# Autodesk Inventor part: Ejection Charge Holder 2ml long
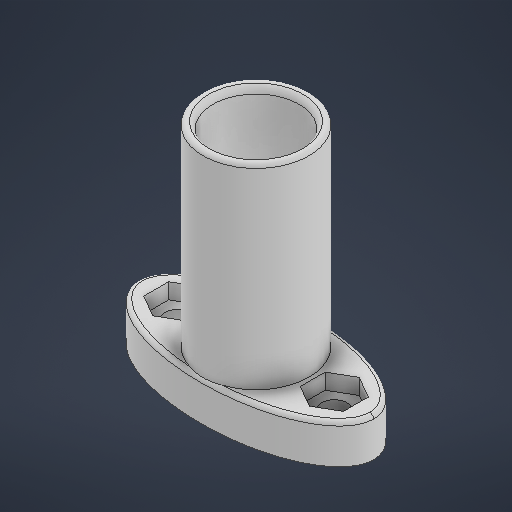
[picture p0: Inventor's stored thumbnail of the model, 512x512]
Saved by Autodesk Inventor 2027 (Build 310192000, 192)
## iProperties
Created: 2026-05
Part Number: Ejection Charge Holder 2ml long
Material: Generisch
Document SubType Name: Modeling
Designer: charl
Density: 1 g/cm^3
Appearance: Vorgabe
Author: charl
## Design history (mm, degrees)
sketch "Skizze1"
  geometry: C1 r 5 at (0, 0); C2 r 10 at (0, 0); 1 further point
  constraints: 2 centre point, 2 coincident, 1 other
  dimensions: "d0" = 10 diameter of C1; "d1" = 7 dimension on C2; "d2" = 15 dimension on C2
extrude "Extrusion1" new body sketch "Skizze1" distance "d3" = 5; taper "d4" = 0 deg
sketch "Skizze4"
  geometry: L1 (-9.979, 3.175)-(-7.229, 1.588); L2 (-7.229, 1.588)-(-7.229, -1.588); L3 (-7.229, -1.588)-(-9.979, -3.175); L4 (-9.979, -3.175)-(-12.729, -1.588); L5 (-12.729, -1.588)-(-12.729, 1.588); L6 (-12.729, 1.588)-(-9.979, 3.175); L7 (0, 7)-(0, 0); L8 (9.979, 3.175)-(7.229, 1.588); L9 (7.229, 1.588)-(7.229, -1.588); L10 (7.229, -1.588)-(9.979, -3.175); L11 (9.979, -3.175)-(12.729, -1.588); L12 (12.729, -1.588)-(12.729, 1.588); L13 (12.729, 1.588)-(9.979, 3.175); C1 r 5 at (0, 0) reference; 6 further points; 1 other entity
  constraints: 26 end point, 8 symmetric about line, 3 vertical alignment, 2 coincident, 2 vertical, 18 other
  dimensions: "d93" = 5.5 distance between parallel lines of L2 L5
extrude "Extrusion3" cut sketch "Skizze4" distance "d22" = 2; taper "d23" = 0 deg
sketch "Skizze5"
  geometry: L1 (-12.729, 1.588)-(-9.979, 3.175) reference; L2 (-7.229, -1.588)-(-9.979, -3.175) reference; L3 (-9.979, 3.175)-(-9.979, -3.175); L4 (-7.229, 1.588)-(-7.229, -1.588) reference; L5 (-12.729, 1.588)-(-7.229, -1.588); L6 (0, 5)-(0, -5); A1 r 5 centre (0, 0) between (0, 5) and (0, -5) reference; 3 further points
  constraints: 6 end point, 2 point on circle, 1 midpoint, 1 symmetric about line, 1 vertical
hole "Bohrung2" sketch "Skizze5" at (-9.979, 0), (9.979, 0) diameter "d24" = 3.2; stored, may be unused: countersink angle "d28" = 90 deg, drill point angle "d30" = 118 deg; dims "d25" = 6, "d26" = 6.3, "d27" = 2, "d29" = 8
sketch "Skizze6"
  geometry: C1 r 5.5 at (0, 0); C2 r 6.75 at (0, 0); 1 further point
  constraints: 2 centre point, 2 coincident
  dimensions: "d31" = 13.5 diameter of C2; "d71" = 11 diameter of C1
extrude "Extrusion4" join sketch "Skizze6" distance "d32" = 25; taper "d33" = 0 deg
fillet "Rundung1" dims "d34" = 1
fillet "Rundung2" dims "d35" = 0.5
workplane "Arbeitsebene6"
sketch "Skizze13"
  geometry: L1 (0, 0)-(0, 2.574); L2 (-1.899, 1)-(1.542, 1); L3 (15, 0)-(-15, 0) reference; L4 (-1.5, 2)-(1.5, 2); L5 (1.5, 2)-(1.5, 0); L6 (1.5, 0)-(-1.5, 0); L7 (-1.5, 0)-(-1.5, 2); L8 (-1.5, 2)-(1.5, 0); L9 (1.5, 2)-(-1.5, 0); 1 further point
  constraints: 16 end point, 3 point on line, 2 horizontal, 2 midpoint, 2 parallel, 1 perpendicular, 1 vertical
  dimensions: "d62" = 1 distance between parallel lines of L3 L2; "d63" = 3 distance of L5.end L6.end
extrude "Extrusion9" cut sketch "Skizze13" distance "d64" = 3; taper "d65" = 0 deg
fillet "Rundung7" dims "d66" = 0.5
fillet "Rundung8" dims "d67" = 0.5
sketch "Skizze14"
  geometry: C1 r 8 at (0, 0); 1 further point
  constraints: 1 centre point, 1 coincident, 1 other
  dimensions: "d68" = 16 diameter of C1
extrude "Extrusion10" cut sketch "Skizze14" distance "d69" = 0.5; taper "d70" = 0 deg
fillet "Rundung9" dims "d75" = 2
workplane "Arbeitsebene12"
sketch "Skizze24"
  geometry: L1 (-1.014, 4.9)-(0.986, 4.9); L2 (0.986, 4.9)-(0.986, 5.918); L3 (-1.014, 5.914)-(-1.014, 4.9); L4 (-1.014, 4.9)-(0.069, 6); L5 (0.986, 4.9)-(-0.119, 5.999); L6 (-4.751, 1.572)-(-3.751, 3.304); L7 (-3.751, 3.304)-(-4.633, 3.813); L8 (-5.628, 2.079)-(-4.751, 1.572); L9 (-4.751, 1.572)-(-5.161, 3.06); L10 (-3.751, 3.304)-(-5.255, 2.896); L11 (-3.736, -3.328)-(-4.736, -1.596); L12 (-4.736, -1.596)-(-5.618, -2.105); L13 (-4.614, -3.835)-(-3.736, -3.328); L14 (-3.736, -3.328)-(-5.231, -2.94); L15 (-4.736, -1.596)-(-5.136, -3.102); L16 (1.014, -4.9)-(-0.986, -4.9); L17 (-0.986, -4.9)-(-0.986, -5.918); L18 (1.014, -5.914)-(1.014, -4.9); L19 (1.014, -4.9)-(-0.069, -6); L20 (-0.986, -4.9)-(0.119, -5.999); L21 (4.751, -1.572)-(3.751, -3.304); L22 (3.751, -3.304)-(4.633, -3.813); L23 (5.628, -2.079)-(4.751, -1.572); L24 (4.751, -1.572)-(5.161, -3.06); L25 (3.751, -3.304)-(5.255, -2.896); L26 (3.736, 3.328)-(4.736, 1.596); L27 (4.736, 1.596)-(5.618, 2.105); L28 (4.614, 3.835)-(3.736, 3.328); L29 (3.736, 3.328)-(5.231, 2.94); L30 (4.736, 1.596)-(5.136, 3.102); A1 r 6 centre (0, 0) between (-1.014, 5.914) and (0.986, 5.918); 18 further points
  constraints: 60 end point, 12 point on line, 4 point on circle, 2 coincident, 1 centre point, 1 horizontal, 1 parallel, 1 perpendicular, 76 other
  dimensions: "d139" = 360 deg dimension on A1.centre L1.start (derived); "d144" = 1.1 distance edge to line of A1 L1; "d145" = 12 diameter of A1; "d146" = 2 distance between parallel lines of L2 L3
extrude "Extrusion17" join sketch "Skizze24" distance "d141" = 15; taper "d142" = 0 deg
fillet "Rundung15" dims "d143" = 0.8
fillet "Rundung16" dims "d147" = 0.5
node "Volumenkörper1"
node "Skizze - Runde Anordnung4" dims "d139" = 360 deg (derived)
other parameters: "d61" = 7
